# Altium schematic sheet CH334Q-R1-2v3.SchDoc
size 209 x 148 mm; PageSetup: Record=PageOptions¦CenterHorizontal=True¦CenterVertical=True¦PrintScale=0.65¦XCorrection=1.00¦YCorrection=1.00¦PrintKind=1¦BorderSize=5000000¦LeftOffset=0¦BottomOffset=0¦Orientation=2¦PaperLength=1000¦PaperWidth=1000¦Scale=100¦PaperSource=7¦PrintQuality=-4¦MediaType=1¦DitherType=10¦PaperKind=16 开 195x270¦PrintScaleMode=1
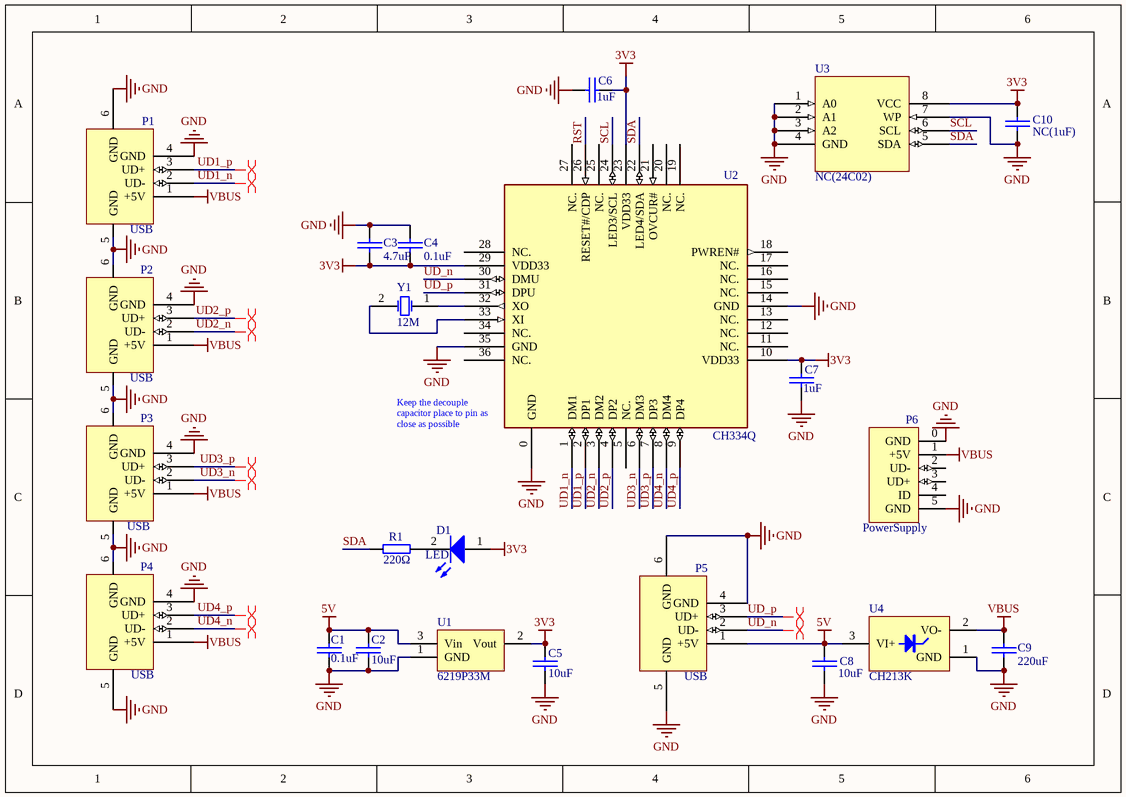
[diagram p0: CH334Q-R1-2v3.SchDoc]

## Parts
C1  0.1uF  [0603_C]
C2  10uF  [0603_C]
C3  4.7uF  [0603_C]
C4  0.1uF  [0603_C]
C5  10uF  [0603_C]
C6  1uF  [0603_C]
C7  1uF  [0603_C]
C8  10uF  [0603_C]
C9  220uF  [CD0.1]
C10  NC(1uF)  [0603_C]
D1  LED  [0603+]
P1  USB  [USBAF]
P2  USB  [USB2.0-A-F-TH_4P-V_13.7mm]
P3  USB  [USB2.0-A-F-TH_4P-V_13.7mm]
P4  USB  [USB2.0-A-F-TH_4P-V_13.7mm]
P5  USB  [USBAF]
P6  PowerSupply  [USBMICROB-02-GXPX-A1T2]
R1  220Ω  [0603_R]
U1  6219P33M  [SOT-23]
U2  CH334Q  [QFN36_6x6]
U3  NC(24C02)  [SOIC-8_150mil]
U4  CH213K  [SOT-23-3]
Y1  12M  [XT_AT49]

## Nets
3V3: C3.1 C4.1 C5.1 C6.2 C7.1 C10.2 D1.1(A) U1.2(Vout) U2.10(VDD33) U2.23(VDD33) U2.29(VDD33) U3.8(VCC)
5V: C1.1 C2.1 C8.1 P5.1(+5V) U1.3(Vin) U4.3(VI+)
GND: C1.2 C2.2 C3.2 C4.2 C5.2 C6.1 C7.2 C8.2 C9.2 C10.1 P1.4(GND) P1.5(GND) P1.6(GND) P2.4(GND) P2.5(GND) P2.6(GND) P3.4(GND) P3.5(GND) P3.6(GND) P4.4(GND) P4.5(GND) P4.6(GND) P5.4(GND) P5.5(GND) P5.6(GND) P6.0(GND) P6.5(GND) U1.1(GND) U2.0(GND) U2.14(GND) U2.35(GND) U3.1(A0) U3.2(A1) U3.3(A2) U3.4(GND) U3.7(WP) U4.1(GND)
VBUS: C9.1 P1.1(+5V) P2.1(+5V) P3.1(+5V) P4.1(+5V) P6.1(+5V) U4.2(VO-)
RST: U2.26(RESET#/CDP)
SCL: U2.24(LED3/SCL) U3.6(SCL)
SDA: R1.1 U2.22(LED4/SDA) U3.5(SDA)
UD1_n: P1.2(UD-) U2.1(DM1)
UD1_p: P1.3(UD+) U2.2(DP1)
UD2_n: P2.2(UD-) U2.3(DM2)
UD2_p: P2.3(UD+) U2.4(DP2)
UD3_n: P3.2(UD-) U2.6(DM3)
UD3_p: P3.3(UD+) U2.7(DP3)
UD4_n: P4.2(UD-) U2.8(DM4)
UD4_p: P4.3(UD+) U2.9(DP4)
UD_n: P5.2(UD-) U2.30(DMU)
UD_p: P5.3(UD+) U2.31(DPU)
NetD1_2: D1.2(K) R1.2
NetU2_32: U2.32(XO) Y1.1(OSC1)
NetU2_33: U2.33(XI) Y1.2(OSC2)

Not connected (* = marked no-connect by the designer): P6 2(UD-) 3(UD+) 4(ID); U2 5(NC.) 11(NC.) 12(NC.) 13(NC.) 15(NC.) 16(NC.) 17(NC.) 18(PWREN#) 19(NC.) 20(NC.) 21(OVCUR#) 25(NC.) 27(NC.) 28(NC.) 34(NC.) 36(NC.)

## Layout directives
differential pair: UD1_n, UD1_p, UD2_n, UD2_p, UD3_n, UD3_p, UD4_n, UD4_p, UD_n, UD_p

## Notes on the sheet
- (near U2) Keep the decouple capacitor place to pin as close as possible

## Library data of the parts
C1-C10 = CAP: Capacitor
D1 = LED: Typical INFRARED GaAs LED
P1-P5 = USB: USB Port
P6 = MicroUSB: MicroUSB Port
R1 = RES
U2 = CH334Q: 4 ports High-Speed USB MTT Hub with over current detect & power control
U3 = 24C01
U4 = CH213K: Ideal Diode 5V*1A
Y1 = XTAL: Crystal Oscillator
